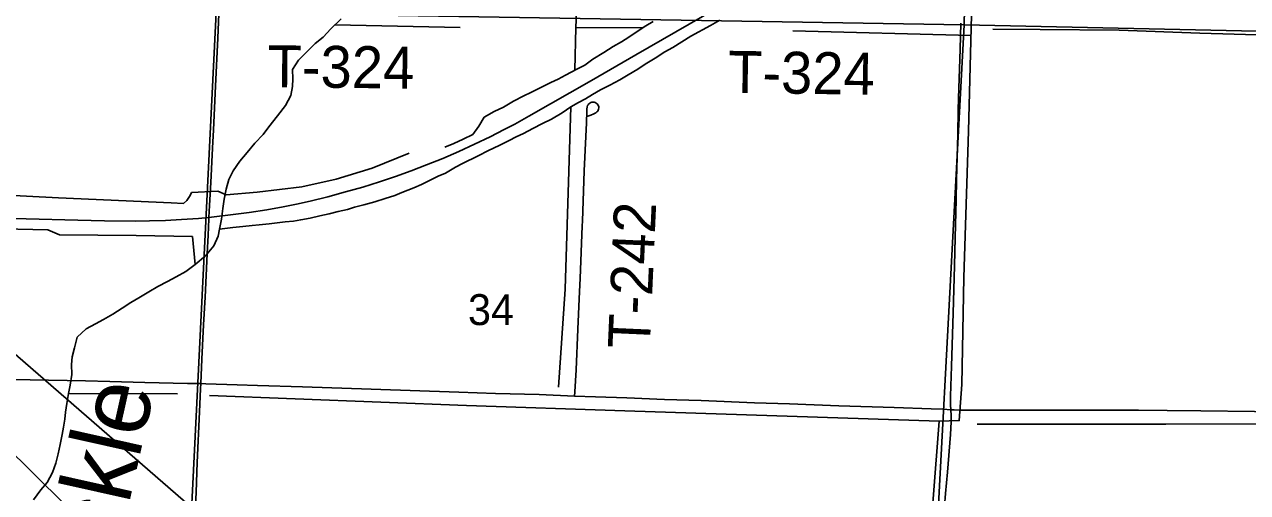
# Model space of a CAD drawing. Extents: x -59 to 43, y 0 to 22.
# Drawn here: x 27.989 to 29.644, y 15.571 to 16.205 of the extents above; entities that cross this region are included whole.
import ezdxf

# ---------------------------------------------------------------- set-up
doc = ezdxf.new("R2010")
doc.units = 0
for name, color, linetype in [('BR_P_Gen_Text', 7, 'Continuous'), ('GM_X_County_Road', 7, 'Continuous'), ('GM_X_Minor_River', 7, 'Continuous'), ('GM_X_Minor_River_Text', 7, 'Continuous'), ('GM_X_Section', 7, 'Continuous'), ('GM_X_Section_Text', 7, 'Continuous'), ('GM_X_Township_Road', 7, 'Continuous'), ('GM_X_Township_Road_Text', 7, 'Continuous'), ('GM_X_US_Route', 7, 'Continuous')]:
    doc.layers.add(name, color=color, linetype=linetype)

msp = doc.modelspace()

# ---------------------------------------------------------------- linework, layer by layer
at = {"layer": 'BR_P_Gen_Text'}
msp.add_lwpolyline([(26.8361, 16.7501), (30.1526, 13.8664), (29.75, 13.8664)], close=True, dxfattribs=at)
at = {"layer": 'GM_X_County_Road'}
for points in [[(28.2384, 15.9442), (28.2394, 15.9602), (28.2411, 15.9912), (28.2435, 16.0378), (28.2447, 16.0627), (28.2476, 16.1217), (28.2505, 16.1869), (28.2521, 16.2199)], [(28.2276, 15.719), (28.2291, 15.7522), (28.2311, 15.7987), (28.2333, 15.836), (28.2362, 15.895), (28.2373, 15.9199), (28.2382, 15.9416), (28.2384, 15.9442)], [(28.215, 15.2143), (28.2115, 15.2255), (28.2096, 15.231), (28.2083, 15.2367), (28.2075, 15.2428), (28.2073, 15.2459), (28.2072, 15.2521), (28.2077, 15.2676), (28.2095, 15.308), (28.2102, 15.3266), (28.211, 15.3452), (28.2148, 15.4291), (28.2158, 15.4508), (28.2183, 15.5037), (28.2212, 15.572), (28.2225, 15.6124), (28.2257, 15.6807), (28.2273, 15.7118), (28.2276, 15.719)]]:
    msp.add_lwpolyline(points, dxfattribs=at)
at = {"layer": 'GM_X_Minor_River'}
for points in [[(28.7463, 16.5073), (28.7431, 16.3915), (28.7351, 16.2013), (28.734, 16.1435)], [(29.2758, 16.4111), (29.2668, 16.0607), (29.2602, 15.8629), (29.2576, 15.7178), (29.2541, 15.6689), (29.2271, 15.6682), (28.8017, 15.6823), (28.5871, 15.6892), (28.2393, 15.703)], [(28.4176, 16.2131), (28.4037, 16.1996), (28.3932, 16.1884), (28.3824, 16.1795), (28.3716, 16.169), (28.3596, 16.1571), (28.3518, 16.1443), (28.3519, 16.1318), (28.3517, 16.1215), (28.3492, 16.1094), (28.3421, 16.0959), (28.3312, 16.0816), (28.3196, 16.067), (28.3118, 16.0565), (28.3009, 16.0446), (28.2904, 16.0322), (28.2804, 16.0203), (28.2714, 16.0071), (28.2655, 15.9954), (28.2618, 15.9822), (28.2593, 15.969), (28.2572, 15.9561), (28.2554, 15.9417), (28.2529, 15.9284), (28.2512, 15.9186), (28.2452, 15.9058), (28.234, 15.8923), (28.2201, 15.8804), (28.2074, 15.8707), (28.1943, 15.8638), (28.1824, 15.8571), (28.1694, 15.8505), (28.1571, 15.8435), (28.1436, 15.8354), (28.1329, 15.8291), (28.1213, 15.821), (28.1083, 15.8129), (28.096, 15.8059), (28.0852, 15.8), (28.0722, 15.793), (28.0602, 15.7818), (28.0565, 15.7675), (28.0536, 15.7554), (28.0527, 15.7447), (28.0528, 15.7314), (28.0507, 15.7167), (28.0486, 15.7057), (28.0464, 15.692), (28.0443, 15.6803), (28.0434, 15.6708), (28.0417, 15.6602), (28.04, 15.65), (28.0374, 15.6367), (28.0346, 15.6239), (28.0313, 15.6114), (28.0269, 15.5986), (28.0194, 15.585), (28.0109, 15.5753), (28.0011, 15.5618)], [(28.2529, 15.9284), (28.2708, 15.9304), (28.2845, 15.9317), (28.297, 15.9333), (28.3065, 15.9339), (28.3202, 15.9352), (28.3309, 15.9369), (28.3416, 15.9382), (28.353, 15.9392), (28.3629, 15.9409), (28.3755, 15.9429), (28.3888, 15.9461), (28.4014, 15.9489), (28.4137, 15.9521), (28.4262, 15.955), (28.4358, 15.9578), (28.448, 15.961), (28.4629, 15.9653), (28.477, 15.9696), (28.49, 15.9739), (28.4996, 15.978), (28.5161, 15.9841), (28.5264, 15.9889), (28.5391, 15.9951), (28.5487, 15.9999), (28.5586, 16.0042), (28.5721, 16.012), (28.5817, 16.0171), (28.6031, 16.0274), (28.6169, 16.0347), (28.6315, 16.0417), (28.6449, 16.0483), (28.6545, 16.0534), (28.6645, 16.0578), (28.6768, 16.0644), (28.6902, 16.0714), (28.7024, 16.0773), (28.7167, 16.0857), (28.7286, 16.0939), (28.7386, 16.0998), (28.7482, 16.1049), (28.7578, 16.1105), (28.7685, 16.1171), (28.7812, 16.1233), (28.7946, 16.1303), (28.8061, 16.1373), (28.8192, 16.1451), (28.8292, 16.1517), (28.8426, 16.1598), (28.8557, 16.1683), (28.8665, 16.1742), (28.8788, 16.182), (28.8907, 16.1894), (28.9175, 16.2041), (28.9302, 16.2111)], [(28.5577, 16.0392), (28.57, 16.0443), (28.5826, 16.0502), (28.5957, 16.0564), (28.6038, 16.0676), (28.6113, 16.0797), (28.6247, 16.0874), (28.6374, 16.0936), (28.6508, 16.1014), (28.6646, 16.1087), (28.6742, 16.1131), (28.688, 16.1201), (28.7014, 16.127), (28.7114, 16.1314), (28.7214, 16.1366), (28.7367, 16.145), (28.7475, 16.1505), (28.7582, 16.1586), (28.7729, 16.1676), (28.7859, 16.1757), (28.7971, 16.1819), (28.807, 16.1882), (28.817, 16.1949), (28.8301, 16.2034), (28.8397, 16.2093)], [(28.4091, 16.2048), (28.5785, 16.2011)], [(28.7351, 16.2013), (28.8262, 16.2008)], [(29.2702, 16.1905), (29.0288, 16.1968)], [(30.3167, 16.1781), (30.2566, 16.178), (30.1946, 16.1769), (30.0925, 16.1806), (30.0127, 16.1817), (29.9102, 16.1851), (29.7962, 16.1886), (29.6879, 16.1906), (29.5797, 16.1937), (29.4707, 16.1976), (29.3636, 16.1987), (29.2997, 16.1991)], [(28.7286, 16.0939), (28.7207, 15.8471), (28.7115, 15.7143)], [(27.5995, 15.9888), (27.7359, 15.9863), (27.7543, 15.9753), (27.8455, 15.9703), (27.8696, 15.9794), (28.0351, 15.9707), (28.1874, 15.9638), (28.2041, 15.9631), (28.2087, 15.9672), (28.213, 15.974), (28.2151, 15.9777), (28.2504, 15.9798), (28.262, 15.9746), (28.3039, 15.9784), (28.3645, 15.9857), (28.4106, 15.9959), (28.4595, 16.0109), (28.5097, 16.0313)], [(27.2516, 15.9562), (27.4524, 15.9454), (27.5891, 15.9365), (27.7176, 15.9376), (27.8983, 15.9302), (28.0203, 15.9273), (28.0365, 15.9205), (28.1402, 15.9194), (28.2162, 15.9181), (28.2201, 15.8804)], [(28.0486, 15.7057), (28.196, 15.7053)], [(29.2271, 15.6682), (29.2187, 15.5631), (29.2034, 15.3879), (29.1902, 15.2225)], [(30.3167, 15.6631), (30.1812, 15.6647), (29.8434, 15.6651), (29.5337, 15.6642), (29.2783, 15.6639)]]:
    msp.add_lwpolyline(points, dxfattribs=at)
at = {"layer": 'GM_X_Section'}
for points in [[(28.2762, 17.2295), (29.2824, 17.2037), (29.2609, 16.2051), (28.2485, 16.2218)], [(29.2824, 17.2037), (30.2784, 17.1834), (30.2413, 16.1837), (29.2609, 16.2051)], [(27.2374, 16.2454), (28.2485, 16.2218), (28.1989, 15.2189), (27.2112, 15.2343), (27.2021, 15.2348)], [(29.2609, 16.2051), (29.207, 15.2007), (28.2121, 15.218), (28.1989, 15.2189), (28.2485, 16.2218)], [(30.2413, 16.1837), (30.2026, 15.1773), (29.2229, 15.1998), (29.207, 15.2007), (29.2609, 16.2051)]]:
    msp.add_lwpolyline(points, close=True, dxfattribs=at)
at = {"layer": 'GM_X_Township_Road'}
for points in [[(29.2426, 15.6837), (29.2424, 15.6903), (29.2424, 15.7021), (29.2438, 15.7425), (29.2459, 15.8146), (29.2476, 15.8786), (29.2486, 15.9171), (29.2499, 15.9681), (29.2505, 15.9948), (29.2521, 16.0569), (29.2528, 16.0892), (29.2532, 16.1054), (29.2552, 16.1719), (29.2562, 16.207)], [(28.7441, 15.9389), (28.7466, 16.0072), (28.7488, 16.0536), (28.7495, 16.0723), (28.75, 16.0878), (28.7502, 16.0909), (28.7507, 16.094)], [(28.7507, 16.094), (28.7511, 16.0955), (28.7518, 16.0968), (28.7529, 16.0981), (28.754, 16.099), (28.7554, 16.0997), (28.7568, 16.1001), (28.7584, 16.1002), (28.7599, 16.1001), (28.7615, 16.0996), (28.7628, 16.0989), (28.7641, 16.0978), (28.765, 16.0967), (28.7657, 16.0954), (28.7661, 16.0939), (28.7661, 16.0924), (28.766, 16.0908), (28.7656, 16.0895), (28.7649, 16.0881), (28.7638, 16.087), (28.7624, 16.0859), (28.7597, 16.0844), (28.7554, 16.0826), (28.7501, 16.0806)], [(28.7335, 15.7021), (28.7339, 15.7079), (28.7354, 15.7376), (28.7378, 15.7928), (28.7401, 15.8438), (28.7409, 15.8615), (28.7439, 15.9329), (28.7441, 15.9389)], [(27.4747, 15.7376), (27.5104, 15.7365), (27.5639, 15.7348), (27.5751, 15.7346), (27.5894, 15.7342), (27.6173, 15.7335), (27.6919, 15.7317), (27.8324, 15.7279), (27.8939, 15.7265), (27.9244, 15.7258), (27.953, 15.7251), (27.9965, 15.7243), (28.0716, 15.7226), (28.1046, 15.7219), (28.1518, 15.7205), (28.2097, 15.7193), (28.2276, 15.719)], [(28.2276, 15.719), (28.2345, 15.7189), (28.2768, 15.7174), (28.3041, 15.7165), (28.365, 15.7148), (28.4582, 15.7113), (28.5769, 15.7075), (28.6266, 15.7057), (28.6856, 15.7041), (28.7335, 15.7021)], [(28.7335, 15.7021), (28.762, 15.7009), (28.8043, 15.6998), (28.8552, 15.6977), (28.9049, 15.696), (28.977, 15.6931), (29.0242, 15.6917), (29.0913, 15.689), (29.1659, 15.6865), (29.2162, 15.685), (29.2324, 15.6844), (29.2426, 15.6837)], [(29.2059, 15.2005), (29.2072, 15.2219), (29.2088, 15.2398), (29.2111, 15.2683), (29.2147, 15.3104), (29.2157, 15.3228), (29.2173, 15.3439), (29.2248, 15.4394), (29.2313, 15.5186), (29.2356, 15.5701), (29.2382, 15.5992), (29.2422, 15.65), (29.2431, 15.6674), (29.2432, 15.6736), (29.2431, 15.676), (29.2426, 15.6837)], [(29.2426, 15.6837), (29.2473, 15.6833), (29.2553, 15.6831), (29.2665, 15.683), (29.3075, 15.6831), (29.4285, 15.6831), (29.4966, 15.6831), (29.5357, 15.6826), (29.5811, 15.682), (29.6538, 15.6813), (29.7166, 15.6808), (29.7539, 15.6805), (29.8432, 15.6799), (29.88, 15.6801), (29.9372, 15.6796), (29.9628, 15.6796), (30.0011, 15.6795), (30.0416, 15.6794), (30.0947, 15.6791), (30.1525, 15.6788), (30.1826, 15.6786), (30.2187, 15.6786), (30.2256, 15.6785)]]:
    msp.add_lwpolyline(points, dxfattribs=at)
at = {"layer": 'GM_X_US_Route'}
msp.add_lwpolyline([(27.8878, 15.9449), (27.991, 15.9422), (28.0612, 15.9404), (28.0972, 15.9397), (28.1395, 15.9392), (28.1581, 15.9393), (28.1796, 15.94), (28.2016, 15.9411), (28.2245, 15.9428), (28.2384, 15.9442), (28.2455, 15.9448), (28.2677, 15.9474), (28.293, 15.9509), (28.3169, 15.9546), (28.3389, 15.9586), (28.3572, 15.9622), (28.3754, 15.9663), (28.3995, 15.9722), (28.4235, 15.9787), (28.4468, 15.9853), (28.4693, 15.9923), (28.4912, 15.9996), (28.5122, 16.0071), (28.5331, 16.0151), (28.555, 16.024), (28.5766, 16.0334), (28.5981, 16.0432), (28.6194, 16.0534), (28.6382, 16.063), (28.6525, 16.0706), (28.6714, 16.0811), (28.7562, 16.1295), (28.8165, 16.1643), (28.9248, 16.2267)], dxfattribs=at)

# ---------------------------------------------------------------- texts
at = {"layer": 'GM_X_Minor_River_Text'}
msp.add_text('Cuckle', height=0.09476, rotation=77.4227, dxfattribs=at).set_placement((28.0809, 15.3342))
at = {"layer": 'GM_X_Section_Text'}
msp.add_text('34', height=0.04186, rotation=0, dxfattribs=at).set_placement((28.5892, 15.7983))
at = {"layer": 'GM_X_Township_Road_Text'}
for s, rotation, p in [('T-324', 359.4361, (28.3177, 16.1205)), ('T-324', 359.1568, (28.9409, 16.113)), ('T-242', 87.4609, (28.8352, 15.7655))]:
    msp.add_text(s, height=0.05682, rotation=rotation, dxfattribs=at).set_placement(p)

doc.saveas('drawing.dxf')
